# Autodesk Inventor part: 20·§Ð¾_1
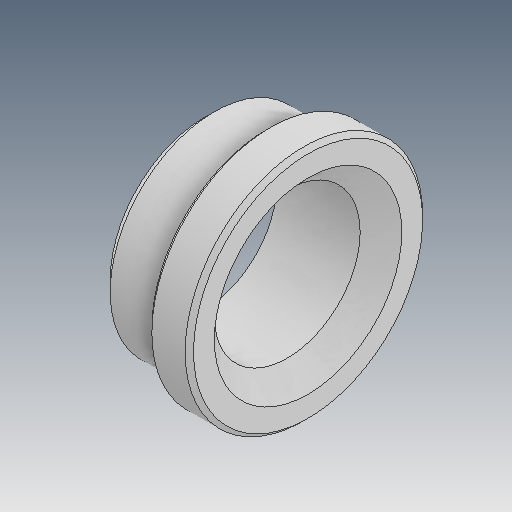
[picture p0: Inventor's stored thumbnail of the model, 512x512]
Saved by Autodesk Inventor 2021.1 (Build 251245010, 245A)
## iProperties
Created: 2019-12
Part Number: 20·§Ð¾_1
Material: Ogólny
Document SubType Name: Modeling
Designer: user
Density: 1 g/cm^3
Appearance: Domyślna
Author: user
Revision Number: ÈÎºÎ
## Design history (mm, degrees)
feature "ÊäÈë1"
node "Bryła1"
